(* Logix 5000 project; controller GracoPd2kDual_Example vendor 1 type 14 code 196 rev 32.11; software revision 32.04 *)
// CompactLogix Controller

TASK MainTask (continuous, watchdog 500 ms) : GRACO_PD2K   // Task Description

MODULES
   Local : vendor 1 type 14 code 196 (5069 0, rev 32.11)
      GRACO_PD2K : ETHERNET-MODULE (Ethernet 192.168.1.50, rev 1.1, Output RPI 100 ms)   // Graco Example PD2K
           GRACO_PD2K:I.Data[0]   // PD2K1 mix unit 1 system mode
           GRACO_PD2K:I.Data[10]   // PD2K1 mix unit 1 actual pump 1 flow rate (cc/min)
           GRACO_PD2K:I.Data[11]   // PD2K1 mix unit 1 actual pump 2 flow rate (cc/min)
           GRACO_PD2K:I.Data[12]   // PD2K1 mix unit 1 actual pump 1 pressure (psi)
           GRACO_PD2K:I.Data[13]   // PD2K1 mix unit 1 actual pump 2 pressure (psi)
           GRACO_PD2K:I.Data[14]   // PD2K1 mix unit 1 active recipe number
           GRACO_PD2K:I.Data[15]   // PD2K1 mix unit 1 active recipe material A
           GRACO_PD2K:I.Data[16]   // PD2K1 mix unit 1 active recipe material B
           GRACO_PD2K:I.Data[17]   // PD2K1 mix unit 1 active recipe flush sequence A
           GRACO_PD2K:I.Data[18]   // PD2K1 mix unit 1 active recipe flush sequence B
           GRACO_PD2K:I.Data[19]   // PD2K1 mix unit 1 active mix ratio SP (A*100 : B)
           GRACO_PD2K:I.Data[1]   // PD2K1 mix unit 1 event flag
           GRACO_PD2K:I.Data[20]   // PD2K1 mix unit 1 active pot life time SP (min)
           GRACO_PD2K:I.Data[21]   // PD2K1 mix unit 1 active job number
           GRACO_PD2K:I.Data[22]   // PD2K1 mix unit 1 job material A sprayed volume (cc)
           GRACO_PD2K:I.Data[23]   // PD2K1 mix unit 1 job material B sprayed volume (cc)
           GRACO_PD2K:I.Data[24]   // PD2K1 mix unit 1 job material solvent sprayed volume (cc)
           GRACO_PD2K:I.Data[25]   // PD2K1 mix unit 1 safety interlock status
           GRACO_PD2K:I.Data[26]   // PD2K1 mix unit 2 system mode
           GRACO_PD2K:I.Data[27]   // PD2K1 mix unit 2 event flag
           GRACO_PD2K:I.Data[28]   // PD2K1 mix unit 2 actual mix flow/pressure (cc/min in flow mode, psi in pressure mode)
           GRACO_PD2K:I.Data[29]   // PD2K1 mix unit 2 actual mix ratio (A*100 : B)
           GRACO_PD2K:I.Data[2]   // PD2K1 mix unit 1 actual mix flow/pressure (cc/min in flow mode, psi in pressure mode)
           GRACO_PD2K:I.Data[30]   // PD2K1 mix unit 2 actual pot life remaining (sec)
           GRACO_PD2K:I.Data[31]   // PD2K1 mix unit 2 gun 2 trigger status
           GRACO_PD2K:I.Data[32]   // PD2K1 mix unit 2 pump 3 status
           GRACO_PD2K:I.Data[33]   // PD2K1 mix unit 2 pump 4 status
           GRACO_PD2K:I.Data[34]   // PD2K1 mix unit 2 pump 3 current material
           GRACO_PD2K:I.Data[35]   // PD2K1 mix unit 2 pump 4 current material
           GRACO_PD2K:I.Data[36]   // PD2K1 mix unit 2 actual pump 3 flow rate (cc/min)
           GRACO_PD2K:I.Data[37]   // PD2K1 mix unit 2 actual pump 4 flow rate (cc/min)
           GRACO_PD2K:I.Data[38]   // PD2K1 mix unit 2 actual pump 3 pressure (psi)
           GRACO_PD2K:I.Data[39]   // PD2K1 mix unit 2 actual pump 4 pressure (psi)
           GRACO_PD2K:I.Data[3]   // PD2K1 mix unit 1 actual mix ratio (A*100 : B)
           GRACO_PD2K:I.Data[40]   // PD2K1 mix unit 2 active recipe number
           GRACO_PD2K:I.Data[41]   // PD2K1 mix unit 2 active recipe material A
           GRACO_PD2K:I.Data[42]   // PD2K1 mix unit 2 active recipe material B
           GRACO_PD2K:I.Data[43]   // PD2K1 mix unit 2 active recipe flush sequence A
           GRACO_PD2K:I.Data[44]   // PD2K1 mix unit 2 active recipe flush sequence B
           GRACO_PD2K:I.Data[45]   // PD2K1 mix unit 2 active mix ratio SP (A*100 : B)
           GRACO_PD2K:I.Data[46]   // PD2K1 mix unit 2 active pot life time SP (min)
           GRACO_PD2K:I.Data[47]   // PD2K1 mix unit 2 active job number
           GRACO_PD2K:I.Data[48]   // PD2K1 mix unit 2 job material A sprayed volume (cc)
           GRACO_PD2K:I.Data[49]   // PD2K1 mix unit 2 job material B sprayed volume (cc)
           GRACO_PD2K:I.Data[4]   // PD2K1 mix unit 1 actual pot life remaining (sec)
           GRACO_PD2K:I.Data[50]   // PD2K1 mix unit 2 job material solvent sprayed volume (cc)
           GRACO_PD2K:I.Data[51]   // PD2K1 mix unit 2 safety interlock status
           GRACO_PD2K:I.Data[52]   // PD2K1 DCS return 0
           GRACO_PD2K:I.Data[53]   // PD2K1 DCS return 1
           GRACO_PD2K:I.Data[54]   // PD2K1 DCS return 2
           GRACO_PD2K:I.Data[55]   // PD2K1 DCS return 3
           GRACO_PD2K:I.Data[56]   // PD2K1 DCS return 4
           GRACO_PD2K:I.Data[57]   // PD2K1 DCS return 5
           GRACO_PD2K:I.Data[58]   // PD2K1 DCS return 6
           GRACO_PD2K:I.Data[59]   // PD2K1 DCS return 7
           GRACO_PD2K:I.Data[5]   // PD2K1 mix unit 1 gun 1 trigger status
           GRACO_PD2K:I.Data[60]   // PD2K1 DCS return 8
           GRACO_PD2K:I.Data[61]   // PD2K1 DCS acknowledge
           GRACO_PD2K:I.Data[6]   // PD2K1 mix unit 1 pump 1 status
           GRACO_PD2K:I.Data[7]   // PD2K1 mix unit 1 pump 2 status
           GRACO_PD2K:I.Data[8]   // PD2K1 mix unit 1 pump 1 current material
           GRACO_PD2K:I.Data[9]   // PD2K1 mix unit 1 pump 2 current material
           GRACO_PD2K:I   // PD2K1 module status
           GRACO_PD2K:O.Data[0]   // PD2K1 mix unit 1 system mode command
           GRACO_PD2K:O.Data[10]   // PD2K1 mix unit 2 system mode command
           GRACO_PD2K:O.Data[11]   // PD2K1 mix unit 2 clear active alarm/deviation
           GRACO_PD2K:O.Data[12]   // PD2K1 mix unit 2 goto recipe number
           GRACO_PD2K:O.Data[13]   // PD2K1 mix unit 2 mix control setpoint (cc/min in flow mode, psi in pressure mode)
           GRACO_PD2K:O.Data[14]   // PD2K1 mix unit 2 mix fill setpoint (cc/min in flow mode, psi in pressure mode)
           GRACO_PD2K:O.Data[15]   // PD2K1 mix unit 2 pump flush sequence number / prime material number
           GRACO_PD2K:O.Data[16]   // PD2K1 mix unit 2 pump flush/prime command
           GRACO_PD2K:O.Data[17]   // PD2K1 mix unit 2 job complete command
           GRACO_PD2K:O.Data[18]   // PD2K1 mix unit 2 gun 2 trigger
           GRACO_PD2K:O.Data[19]   // PD2K1 mix unit 2 fluid control mode (0=flow, 1=pressure)
           GRACO_PD2K:O.Data[1]   // PD2K1 mix unit 1 clear active alarm/deviation
           GRACO_PD2K:O.Data[20]   // PD2K1 DCS argument 0
           GRACO_PD2K:O.Data[21]   // PD2K1 DCS argument 1
           GRACO_PD2K:O.Data[22]   // PD2K1 DCS argument 2
           GRACO_PD2K:O.Data[23]   // PD2K1 DCS argument 3
           GRACO_PD2K:O.Data[24]   // PD2K1 DCS argument 4
           GRACO_PD2K:O.Data[25]   // PD2K1 DCS argument 5
           GRACO_PD2K:O.Data[26]   // PD2K1 DCS argument 6
           GRACO_PD2K:O.Data[27]   // PD2K1 DCS argument 7
           GRACO_PD2K:O.Data[28]   // PD2K1 DCS argument 8
           GRACO_PD2K:O.Data[29]   // PD2K1 DCS command
           GRACO_PD2K:O.Data[2]   // PD2K1 mix unit 1 goto recipe number
           GRACO_PD2K:O.Data[3]   // PD2K1 mix unit 1 mix control setpoint (cc/min in flow mode, psi in pressure mode)
           GRACO_PD2K:O.Data[4]   // PD2K1 mix unit 1 mix fill setpoint (cc/min in flow mode, psi in pressure mode)
           GRACO_PD2K:O.Data[5]   // PD2K1 mix unit 1 pump flush sequence number / prime material number
           GRACO_PD2K:O.Data[6]   // PD2K1 mix unit 1 pump flush/prime command
           GRACO_PD2K:O.Data[7]   // PD2K1 mix unit 1 job complete command
           GRACO_PD2K:O.Data[8]   // PD2K1 mix unit 1 gun 1 trigger
           GRACO_PD2K:O.Data[9]   // PD2K1 mix unit 1 fluid control mode (0=flow, 1=pressure)
           GRACO_PD2K:O   // PD2K1 module commands
           GRACO_PD2K:C   // PD2K1 module configuration
END_MODULES

TYPE GracoCore_TypeDateTime :
STRUCT
   year : DINT;   // year (yyyy)
   month : DINT;   // month (1=January, 2=February...12=December)
   dayOfMonth : DINT;   // day of the month (1-31)
   dayOfWeek : DINT;   // day of the week (1=Monday, 2=Tuesday...7=Sunday)
   hour : DINT;   // hour (0-23)
   min : DINT;   // min (0-59)
   sec : DINT;   // second (0-59)
END_STRUCT
END_TYPE

TYPE GracoPD2K_TypeRecipe :
STRUCT
   materialA : DINT;   // Material number for component A
   materialB : DINT;   // Material number for component B
   flushSeqA : DINT;   // Flush sequence number for component A
   flushSeqB : DINT;   // Flush sequence number for component B
   mixRatioSP : DINT;   // Mix ratio setpoint (A*100 : B)
   potLifeTimeSP : DINT;   // Pot life time setpoint (min)
END_STRUCT
END_TYPE

TYPE GracoPd2kDual_TypePd2kDualStatus :
STRUCT
   gunTriggerStatus1 : BOOL;   // gun 1 trigger status (1 = on)
   gunTriggerStatus2 : BOOL;   // gun 2 trigger status (1 = on)
   mixUnit1 : GracoPd2kDual_TypePd2kMixUnitStatus;   // mix unit 1
   mixUnit2 : GracoPd2kDual_TypePd2kMixUnitStatus;   // mix unit 2
   pump1 : GracoPd2kDual_TypePd2kPump;   // pump 1
   pump2 : GracoPd2kDual_TypePd2kPump;   // pump 2
   pump3 : GracoPd2kDual_TypePd2kPump;   // pump 3
   pump4 : GracoPd2kDual_TypePd2kPump;   // pump 4
   dcsReturn0 : DINT;   // DCS return 0
   dcsReturn1 : DINT;   // DCS return 1
   dcsReturn2 : DINT;   // DCS return 2
   dcsReturn3 : DINT;   // DCS return 3
   dcsReturn4 : DINT;   // DCS return 4
   dcsReturn5 : DINT;   // DCS return 5
   dcsReturn6 : DINT;   // DCS return 6
   dcsReturn7 : DINT;   // DCS return 7
   dcsReturn8 : DINT;   // DCS return 8
   dcsAck : DINT;   // DCS acknowledge
END_STRUCT
END_TYPE

TYPE GracoPd2kDual_TypePd2kMixUnitStatus :
STRUCT
   eventFlag : BOOL;   // event flag
   standby : BOOL;   // in standby
   interlockStatus : BOOL;   // interlock status
   systemMode : DINT;   // system mode
   systemModeFlags : GracoPd2kDual_TypePd2kSystemModeFlags;   // system mode flags
   actualMixFlow : DINT;   // actual mix flow (cc/min)
   actualMixRatio : DINT;   // actual mix ratio
   actualPotLifeRemaining : DINT;   // actual pot life remaining
   activeRecipeNum : DINT;   // active recipe number
   activeMaterialA : DINT;   // active material A
   activeMaterialB : DINT;   // active material B
   activeFlushSeqA : DINT;   // active flush sequence A
   activeFlushSeqB : DINT;   // active flush sequence B
   activeRatioSP : DINT;   // active ratio SP
   activePotLifeSP : DINT;   // active pot life SP
   activeJobNum : DINT;   // active job number
   jobSprayVolA : DINT;   // job sprayed volume A (cc)
   jobSprayVolB : DINT;   // job sprayed volume B (cc)
   jobSolventVol : DINT;   // job solvent volume used (cc)
END_STRUCT
END_TYPE

TYPE GracoPd2kDual_TypePd2kPump :
STRUCT
   status : DINT;   // pump status
   statusFlags : GracoPd2kDual_TypePd2kPumpStatusFlags;   // pump status flags
   actualMaterial : DINT;   // actual material number
   actualFlowRate : DINT;   // actual flow rate (cc/min)
   actualFluidPres : DINT;   // actual fluid pressure (psi)
END_STRUCT
END_TYPE

TYPE GracoPd2kDual_TypePd2kPumpStatusFlags :
STRUCT
   off : BOOL;   // off
   standby : BOOL;   // in standby
   busy : BOOL;   // busy
   flushing : BOOL;   // flushing
   priming : BOOL;   // priming
END_STRUCT
END_TYPE

TYPE GracoPd2kDual_TypePd2kSystemModeFlags :
STRUCT
   pumpOff : BOOL;   // pump off
   colorChange : BOOL;   // color change enabled
   colorChangePurgeA : BOOL;   // color change purging component A
   colorChangePurgeB : BOOL;   // color change purging component B
   colorChangeFilling : BOOL;   // color change filling
   mixFill : BOOL;   // mix fill
   mix : BOOL;   // mixing
   mixIdle : BOOL;   // mix idle
   purgeA : BOOL;   // purging component A
   purgeB : BOOL;   // purging component B
   standbyMixReady : BOOL;   // standby mix ready
   standbyFillReady : BOOL;   // standby fill ready
   standbyMixNotReady : BOOL;   // standby mix not ready
   standbyAlarm : BOOL;   // standby alarm
   lineFillingFlushing : BOOL;   // line is filling or flushing
   pumpPrimeFlush : BOOL;   // pump is priming or flushing
   maintCalibration : BOOL;   // maintenance/calibration
   mixSolventPush : BOOL;   // mix solvent push
END_STRUCT
END_TYPE

TYPE STRING4 :   // string type
STRUCT
   LEN : DINT;
   DATA : SINT[4];
END_STRUCT
END_TYPE

TYPE STRING9 :   // string type
STRUCT
   LEN : DINT;
   DATA : SINT[9];
END_STRUCT
END_TYPE

ADD_ON_INSTRUCTION GracoCore_DecodeDateTime   (* revision 1.0 *)
// Help:
// Convert from Graco-formatted date and time data into a UDT.
VAR_IN_OUT
   dateSource : DINT; {required}
   timeSource : DINT; {required}
   dateTimeDest : GracoCore_TypeDateTime; {required}
END_VAR
VAR
   buffer : DINT; {access None}
END_VAR

ROUTINE Logic   (* ladder *)
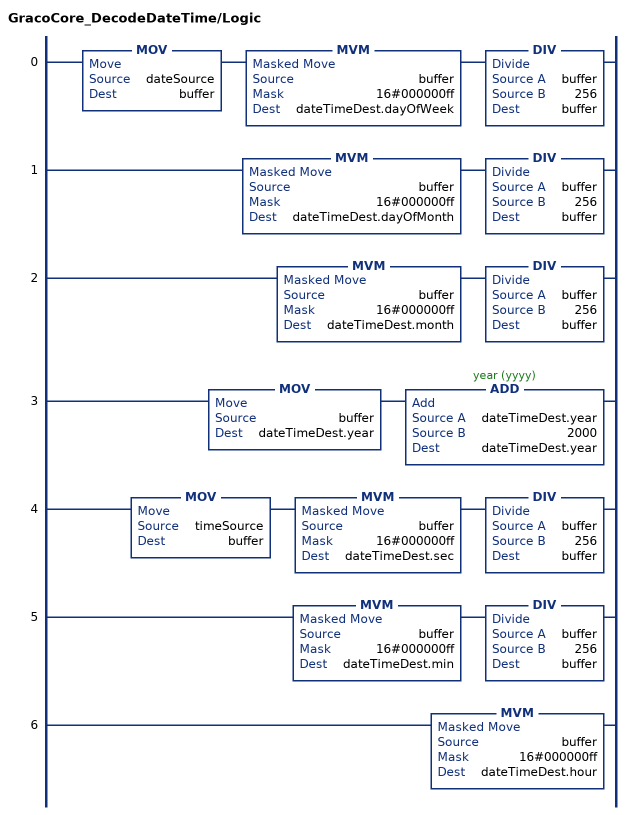
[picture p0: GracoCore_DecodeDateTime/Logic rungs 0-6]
   0: MOV(dateSource,buffer)MVM(buffer,16#000000ff,dateTimeDest.dayOfWeek)DIV(buffer,256,buffer);
   1: MVM(buffer,16#000000ff,dateTimeDest.dayOfMonth)DIV(buffer,256,buffer);
   2: MVM(buffer,16#000000ff,dateTimeDest.month)DIV(buffer,256,buffer);
   3: MOV(buffer,dateTimeDest.year)ADD(dateTimeDest.year,2000,dateTimeDest.year);
   4: MOV(timeSource,buffer)MVM(buffer,16#000000ff,dateTimeDest.sec)DIV(buffer,256,buffer);
   5: MVM(buffer,16#000000ff,dateTimeDest.min)DIV(buffer,256,buffer);
   6: MVM(buffer,16#000000ff,dateTimeDest.hour);
END_ROUTINE
END_ADD_ON_INSTRUCTION

ADD_ON_INSTRUCTION GracoCore_DecodeEventCode   (* revision 1.0 *)
// Help:
// Parses an event code String (max 4 characters) into a series of ASCII values stored in DINTs. These can then be written to a Graco CGM.
VAR_IN_OUT
   source : DINT; {required}
   dest : STRING4; {required}
END_VAR
VAR
   buffer : DINT; {access None}
END_VAR

ROUTINE Logic   (* ladder *)
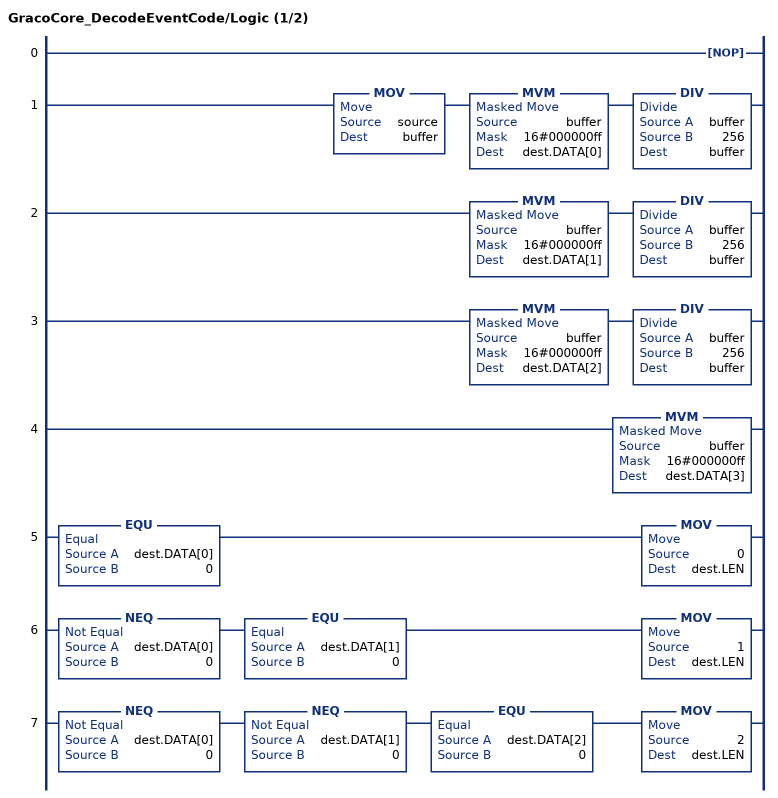
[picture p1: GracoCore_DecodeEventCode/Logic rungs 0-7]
   0: NOP();
   1: MOV(source,buffer)MVM(buffer,16#000000ff,dest.DATA[0])DIV(buffer,256,buffer);
   2: MVM(buffer,16#000000ff,dest.DATA[1])DIV(buffer,256,buffer);
   3: MVM(buffer,16#000000ff,dest.DATA[2])DIV(buffer,256,buffer);
   4: MVM(buffer,16#000000ff,dest.DATA[3]);
   5: EQU(dest.DATA[0],0)MOV(0,dest.LEN);
   6: NEQ(dest.DATA[0],0)EQU(dest.DATA[1],0)MOV(1,dest.LEN);
   7: NEQ(dest.DATA[0],0)NEQ(dest.DATA[1],0)EQU(dest.DATA[2],0)MOV(2,dest.LEN);
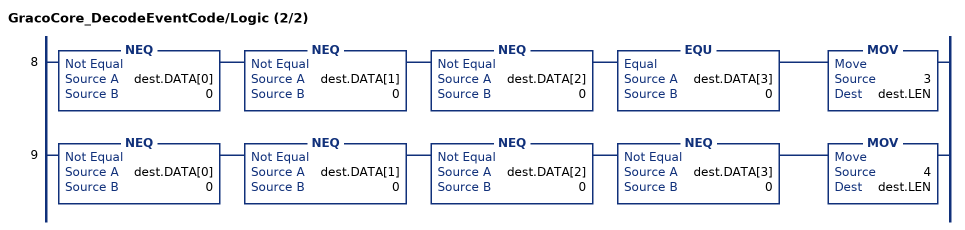
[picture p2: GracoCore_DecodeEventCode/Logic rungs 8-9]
   8: NEQ(dest.DATA[0],0)NEQ(dest.DATA[1],0)NEQ(dest.DATA[2],0)EQU(dest.DATA[3],0)MOV(3,dest.LEN);
   9: NEQ(dest.DATA[0],0)NEQ(dest.DATA[1],0)NEQ(dest.DATA[2],0)NEQ(dest.DATA[3],0)MOV(4,dest.LEN);
END_ROUTINE
END_ADD_ON_INSTRUCTION

ADD_ON_INSTRUCTION GracoCore_DecodeUserID   (* revision 1.0 *)
// Help:
// Parses a user ID from a series of characters stored in DINTs into a Rockwell String (9 characters max).
VAR_IN_OUT
   source1 : DINT; {required}
   source2 : DINT; {required}
   source3 : DINT; {required}
   dest : STRING9; {required}
END_VAR
VAR
   buffer : DINT; {access None}
END_VAR

ROUTINE Logic   (* ladder *)
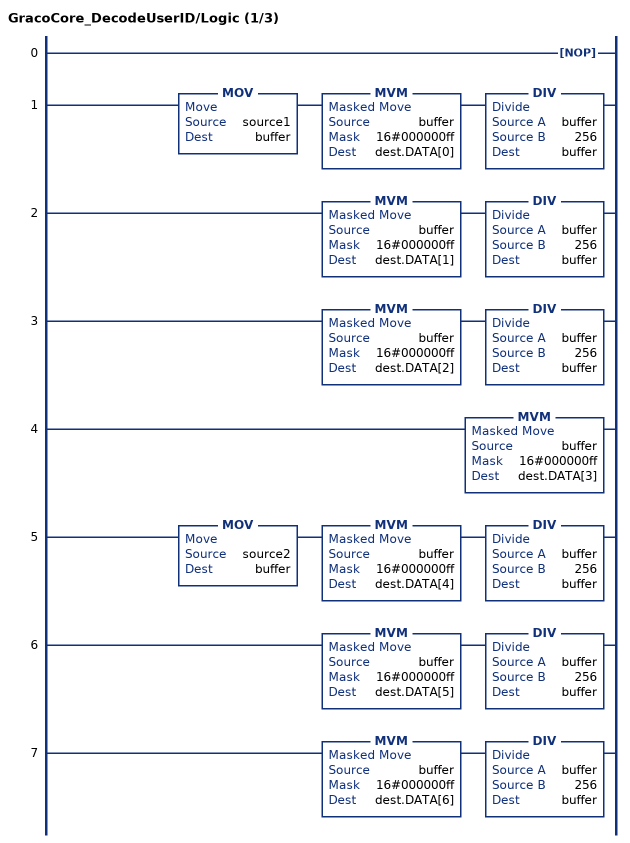
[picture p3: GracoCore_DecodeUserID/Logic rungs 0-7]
   0: NOP();
   1: MOV(source1,buffer)MVM(buffer,16#000000ff,dest.DATA[0])DIV(buffer,256,buffer);
   2: MVM(buffer,16#000000ff,dest.DATA[1])DIV(buffer,256,buffer);
   3: MVM(buffer,16#000000ff,dest.DATA[2])DIV(buffer,256,buffer);
   4: MVM(buffer,16#000000ff,dest.DATA[3]);
   5: MOV(source2,buffer)MVM(buffer,16#000000ff,dest.DATA[4])DIV(buffer,256,buffer);
   6: MVM(buffer,16#000000ff,dest.DATA[5])DIV(buffer,256,buffer);
   7: MVM(buffer,16#000000ff,dest.DATA[6])DIV(buffer,256,buffer);
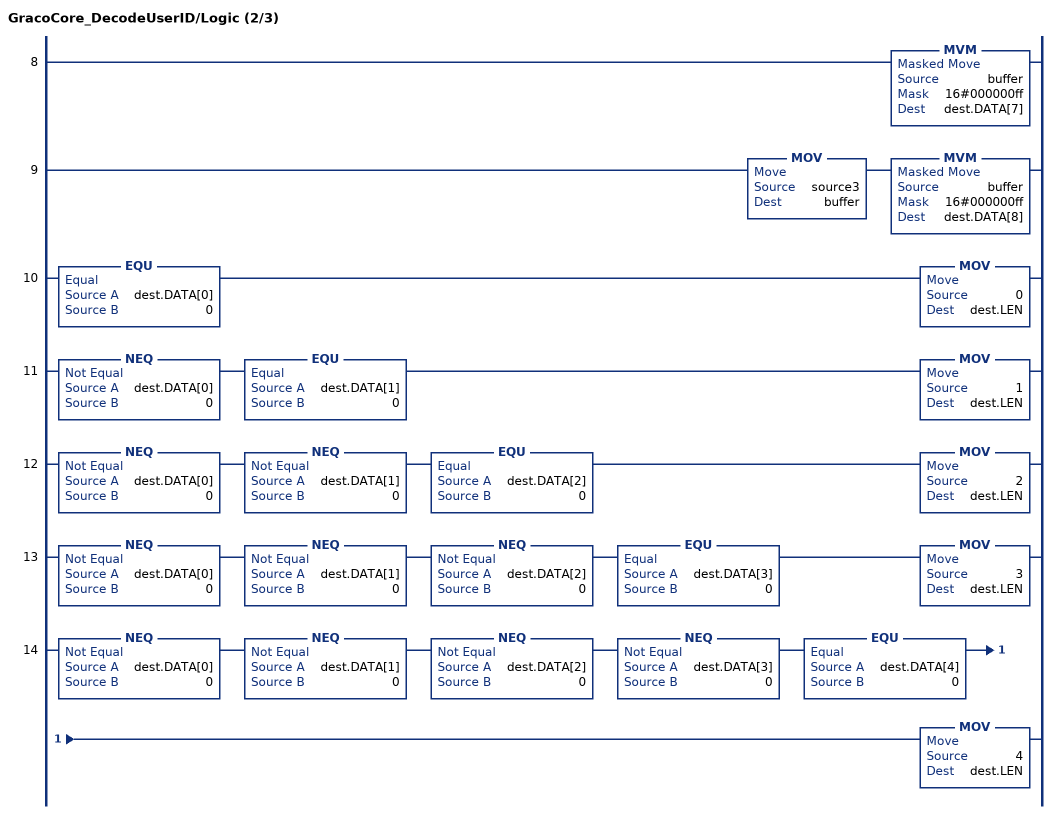
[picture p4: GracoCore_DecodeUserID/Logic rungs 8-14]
   8: MVM(buffer,16#000000ff,dest.DATA[7]);
   9: MOV(source3,buffer)MVM(buffer,16#000000ff,dest.DATA[8]);
   10: EQU(dest.DATA[0],0)MOV(0,dest.LEN);
   11: NEQ(dest.DATA[0],0)EQU(dest.DATA[1],0)MOV(1,dest.LEN);
   12: NEQ(dest.DATA[0],0)NEQ(dest.DATA[1],0)EQU(dest.DATA[2],0)MOV(2,dest.LEN);
   13: NEQ(dest.DATA[0],0)NEQ(dest.DATA[1],0)NEQ(dest.DATA[2],0)EQU(dest.DATA[3],0)MOV(3,dest.LEN);
   14: NEQ(dest.DATA[0],0)NEQ(dest.DATA[1],0)NEQ(dest.DATA[2],0)NEQ(dest.DATA[3],0)EQU(dest.DATA[4],0)MOV(4,dest.LEN);
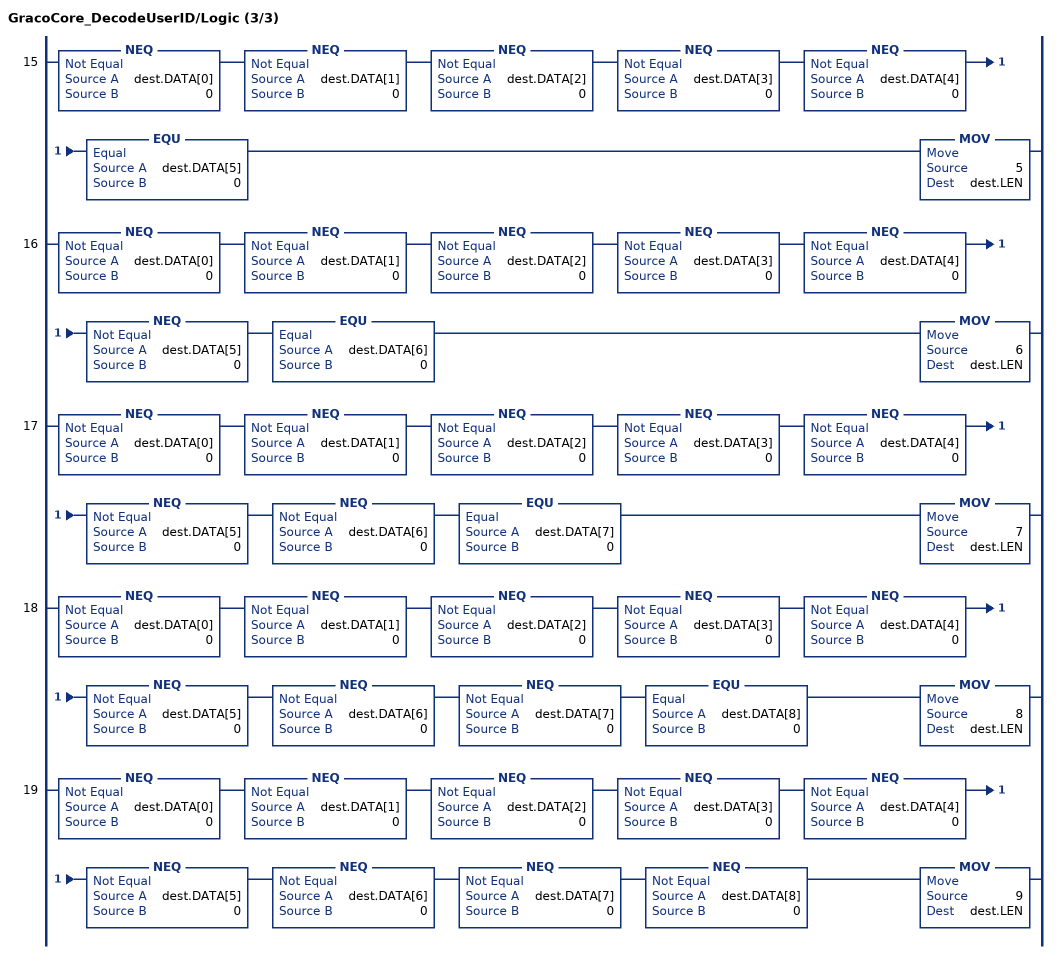
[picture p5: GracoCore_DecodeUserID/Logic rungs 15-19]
   15: NEQ(dest.DATA[0],0)NEQ(dest.DATA[1],0)NEQ(dest.DATA[2],0)NEQ(dest.DATA[3],0)NEQ(dest.DATA[4],0)EQU(dest.DATA[5],0)MOV(5,dest.LEN);
   16: NEQ(dest.DATA[0],0)NEQ(dest.DATA[1],0)NEQ(dest.DATA[2],0)NEQ(dest.DATA[3],0)NEQ(dest.DATA[4],0)NEQ(dest.DATA[5],0)EQU(dest.DATA[6],0)MOV(6,dest.LEN);
   17: NEQ(dest.DATA[0],0)NEQ(dest.DATA[1],0)NEQ(dest.DATA[2],0)NEQ(dest.DATA[3],0)NEQ(dest.DATA[4],0)NEQ(dest.DATA[5],0)NEQ(dest.DATA[6],0)EQU(dest.DATA[7],0)MOV(7,dest.LEN);
   18: NEQ(dest.DATA[0],0)NEQ(dest.DATA[1],0)NEQ(dest.DATA[2],0)NEQ(dest.DATA[3],0)NEQ(dest.DATA[4],0)NEQ(dest.DATA[5],0)NEQ(dest.DATA[6],0)NEQ(dest.DATA[7],0)EQU(dest.DATA[8],0)MOV(8,dest.LEN);
   19: NEQ(dest.DATA[0],0)NEQ(dest.DATA[1],0)NEQ(dest.DATA[2],0)NEQ(dest.DATA[3],0)NEQ(dest.DATA[4],0)NEQ(dest.DATA[5],0)NEQ(dest.DATA[6],0)NEQ(dest.DATA[7],0)NEQ(dest.DATA[8],0)MOV(9,dest.LEN);
END_ROUTINE
END_ADD_ON_INSTRUCTION

ADD_ON_INSTRUCTION GracoCore_EncodeUserID   (* revision 1.0 *)
// Help:
// Parses a user ID String (max 9 characters) into a series of ASCII values stored in DINTs. These can then be written to a Graco CGM.
VAR_IN_OUT
   source : STRING9; {required}
   dest1 : DINT; {required}
   dest2 : DINT; {required}
   dest3 : DINT; {required}
END_VAR
VAR
   buffer : DINT; {access None}
END_VAR

ROUTINE Logic   (* ladder *)
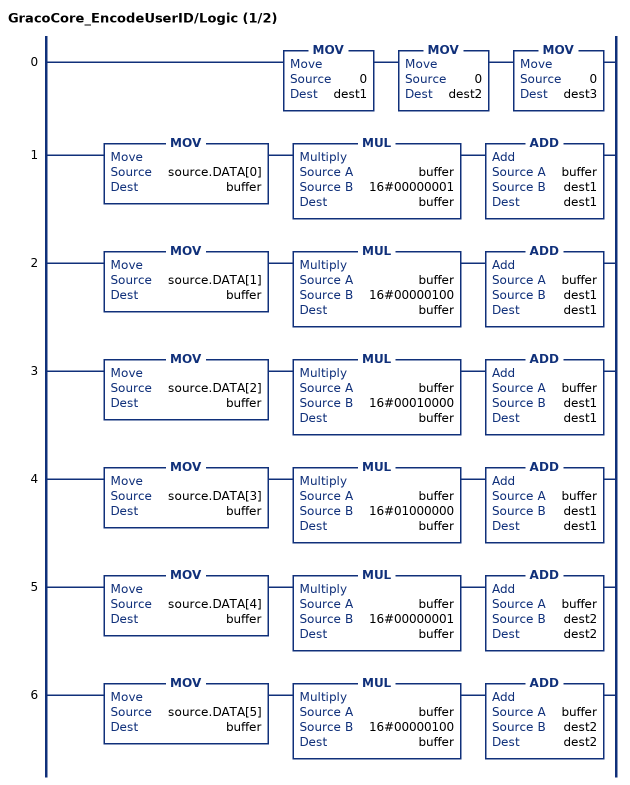
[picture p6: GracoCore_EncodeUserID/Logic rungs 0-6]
   0: MOV(0,dest1)MOV(0,dest2)MOV(0,dest3);
   1: MOV(source.DATA[0],buffer)MUL(buffer,16#00000001,buffer)ADD(buffer,dest1,dest1);
   2: MOV(source.DATA[1],buffer)MUL(buffer,16#00000100,buffer)ADD(buffer,dest1,dest1);
   3: MOV(source.DATA[2],buffer)MUL(buffer,16#00010000,buffer)ADD(buffer,dest1,dest1);
   4: MOV(source.DATA[3],buffer)MUL(buffer,16#01000000,buffer)ADD(buffer,dest1,dest1);
   5: MOV(source.DATA[4],buffer)MUL(buffer,16#00000001,buffer)ADD(buffer,dest2,dest2);
   6: MOV(source.DATA[5],buffer)MUL(buffer,16#00000100,buffer)ADD(buffer,dest2,dest2);
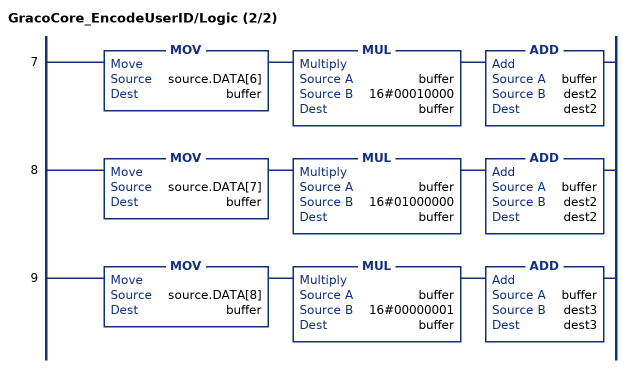
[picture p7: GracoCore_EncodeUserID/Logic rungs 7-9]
   7: MOV(source.DATA[6],buffer)MUL(buffer,16#00010000,buffer)ADD(buffer,dest2,dest2);
   8: MOV(source.DATA[7],buffer)MUL(buffer,16#01000000,buffer)ADD(buffer,dest2,dest2);
   9: MOV(source.DATA[8],buffer)MUL(buffer,16#00000001,buffer)ADD(buffer,dest3,dest3);
END_ROUTINE
END_ADD_ON_INSTRUCTION

ADD_ON_INSTRUCTION GracoCore_Step   (* revision 1.0 *)
// Help:
// An implementation of the step pattern, useful for sequences in ladder logic.
VAR_INPUT
   doneTrigger : BOOL; {access None, visible}
   preCond : BOOL; {visible}
END_VAR
VAR_OUTPUT
   isDone : BOOL; {access Read Only, visible}
   isRunning : BOOL; {access None, visible}
END_VAR

ROUTINE Logic   (* ladder *)
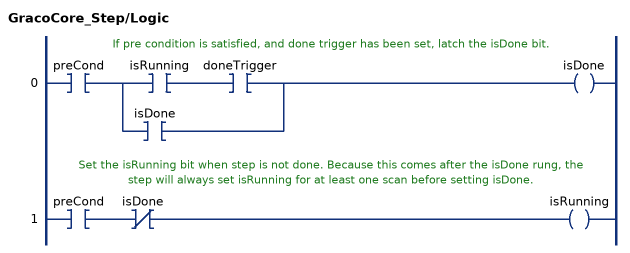
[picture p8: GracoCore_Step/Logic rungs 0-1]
   // If pre condition is satisfied, and done trigger has been set, latch the isDone bit.
   0: XIC(preCond)[XIC(isRunning) XIC(doneTrigger) ,XIC(isDone) ]OTE(isDone);
   // Set the isRunning bit when step is not done. Because this comes after the isDone rung, the step will always set isRunning for at least one scan before setting isDone.
   1: XIC(preCond)XIO(isDone)OTE(isRunning);
END_ROUTINE
END_ADD_ON_INSTRUCTION

ADD_ON_INSTRUCTION GracoPd2kDual_MainCtrl   (* revision 1.0 *)
// Help:
// Provides several inputs for controlling the PD2K proportioner (e.g. system mode, setpoints).
// The enable input must be on for any other inputs to take effect. The boolean command inputs each function like execute inputs, meaning the command will automatically reset these once set to true.
// The current control mode setting (pressure or flow) determines which of the setpoint inputs are written to the PD2K system. This switches automatically when the control mode is changed.
// State Codes:
// * 0000 (IDLE) - Idle
// * 3000 (VALID) - Valid
// * 8000 (ERROR) - Invalid mix unit number
VAR_INPUT
   i_clearAlarm : BOOL; {visible}   // Clear alarm
   i_completeJob : BOOL; {visible}   // Complete job
   i_ctrlMode : BOOL; {visible}   // Ctrl mode SP (0=flow, 1=pressure)
   i_enable : BOOL; {visible}   // Enable command
   i_mix : BOOL; {visible}   // Goto mix
   i_mixFill : BOOL; {visible}   // Goto mix fill
   i_powerOff : BOOL; {visible}   // Power off
   i_powerOn : BOOL; {visible}   // Power on
   i_quickStop : BOOL; {visible}   // Goto quick stop
   i_recipePurge : BOOL; {visible}   // Goto recipe purge
   i_standby : BOOL; {visible}   // Goto standby
   i_mixUnitNum : DINT; {visible}   // Mix unit number (1-2)
   i_flowCtrlSP : DINT; {visible}   // Flow control setpoint (cc/min)
   i_presCtrlSP : DINT; {visible}   // Pressure control setpoint (psi)
END_VAR
VAR_IN_OUT
   io_moduleStatus : DINT[62]; {required}   // Data from module to PLC
   io_moduleCmds : DINT[30]; {required}   // Data from PLC to module
END_VAR
VAR_OUTPUT
   o_aborted : BOOL; {access Read Only, visible}   // Command aborted flag
   o_busy : BOOL; {access Read Only, visible}   // Busy flag
   o_error : BOOL; {access Read Only, visible}   // Error flag
   o_valid : BOOL; {access Read Only, visible}   // Command valid flag
   o_state : DINT; {access Read Only, visible}   // Command state
END_VAR
VAR
   clearAlmPBTmr : TIMER := (PRE := 250); {access None}   // Clear alarm pushbutton timer
   jobCompletePBTmr : TIMER := (PRE := 250); {access None}   // Job complete input timer
   mixFillPBTmr : TIMER := (PRE := 250); {access None}   // Mix fill input timer
   mixPBTmr : TIMER := (PRE := 250); {access None}   // Mix input timer
   ons : DINT; {access None}   // oneshot
   powerOnPBTmr : TIMER := (PRE := 250); {access None}   // Power on input timer
   pumpIsOff : BOOL; {access None}   // Pump is off
   purgePBTmr : TIMER := (PRE := 250); {access None}   // Purge input timer
   quickStopPBTmr : TIMER := (PRE := 250); {access None}   // Quick stop input timer
   isStandby : BOOL; {access None}   // System is in standby
   toStandbyPBTmr : TIMER := (PRE := 250); {access None}   // Standby input timer
   _mixUnitNum : DINT; {access None}   // Mix unit number (internal)
   mixUnitNumOK : BOOL; {access None}   // Mix unit number OK
   systemCmdAvailable : BOOL; {access None}   // System command register is available
   powerOnOffSetTrigger : BOOL; {access None}   // Power on/off set trigger
   powerOnOffResetTrigger : BOOL; {access None}   // Power on/off reset trigger
   quickStopSetTrigger : BOOL; {access None}   // Quick stop set trigger
   quickStopResetTrigger : BOOL; {access None}   // Quick stop reset trigger
   mixFillSetTrigger : BOOL; {access None}   // Mix fill set trigger
   mixFillResetTrigger : BOOL; {access None}   // Mix fill reset trigger
   mixSetTrigger : BOOL; {access None}   // Mix set trigger
   mixResetTrigger : BOOL; {access None}   // Mix reset trigger
   toStandbySetTrigger : BOOL; {access None}   // Standby set trigger
   toStandbyResetTrigger : BOOL; {access None}   // Standby reset trigger
   purgeSetTrigger : BOOL; {access None}   // Purge set trigger
   purgeResetTrigger : BOOL; {access None}   // Purge reset trigger
   state_idle : DINT; {access None}
   state_checkInputs : DINT; {access None}
   state_update : DINT; {access None}
   _nextState : DINT; {access None}
   state_errorInvalidMixUnitNum : DINT; {access None}
END_VAR

ROUTINE Logic   (* ladder *)
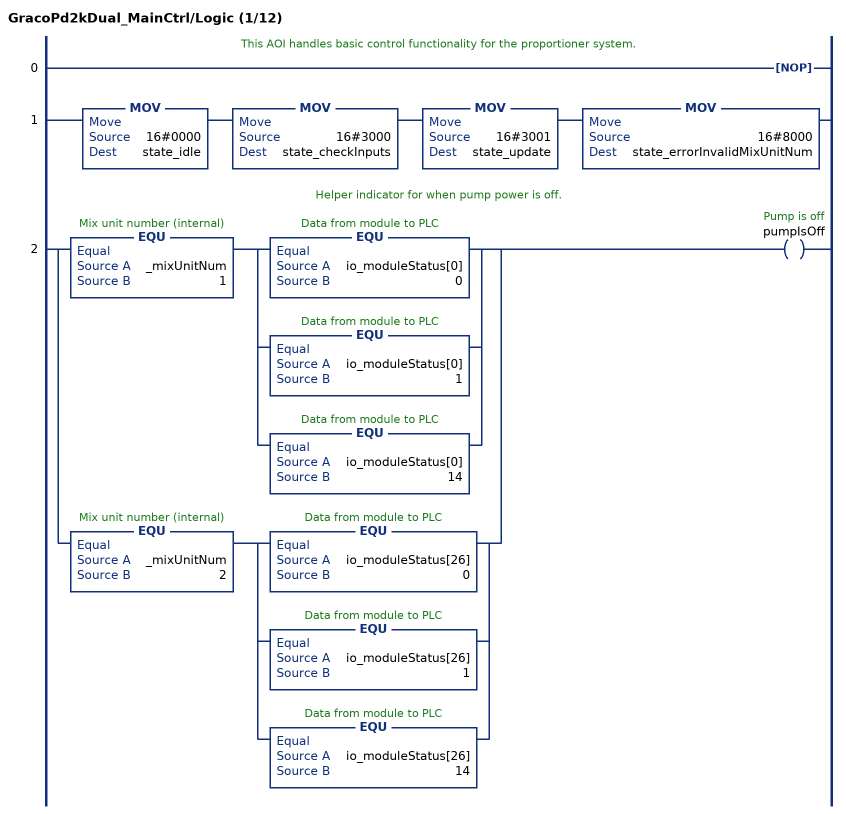
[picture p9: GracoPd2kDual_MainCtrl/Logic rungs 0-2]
   // This AOI handles basic control functionality for the proportioner system.
   0: NOP();
   1: MOV(16#0000,state_idle)MOV(16#3000,state_checkInputs)MOV(16#3001,state_update)MOV(16#8000,state_errorInvalidMixUnitNum);
   // Helper indicator for when pump power is off.
   2: [EQU(_mixUnitNum,1) [EQU(io_moduleStatus[0],0) ,EQU(io_moduleStatus[0],1) ,EQU(io_moduleStatus[0],14) ] ,EQU(_mixUnitNum,2) [EQU(io_moduleStatus[26],0) ,EQU(io_moduleStatus[26],1) ,EQU(io_moduleStatus[26],14) ] ]OTE(pumpIsOff);
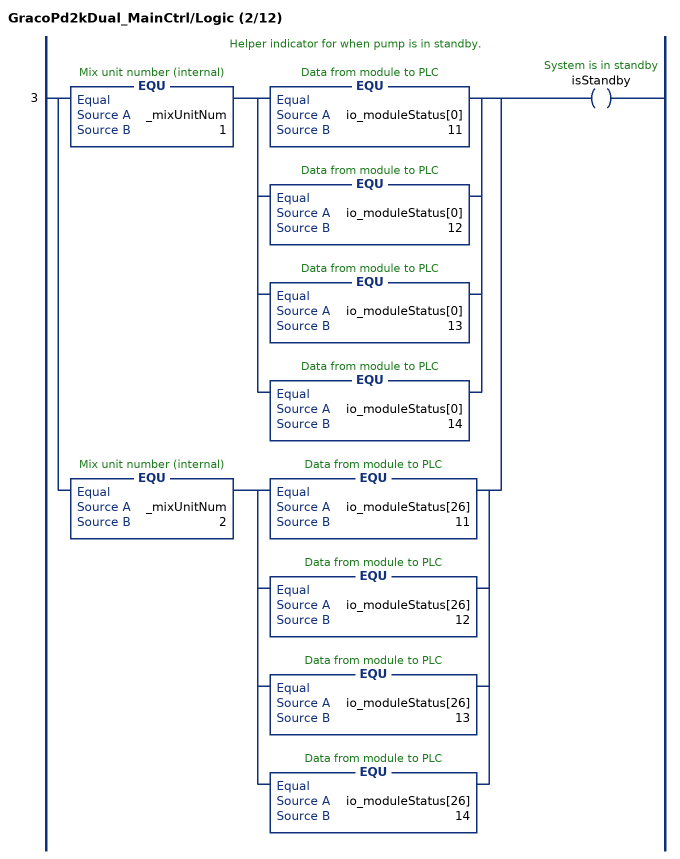
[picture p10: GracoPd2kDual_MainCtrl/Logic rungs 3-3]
   // Helper indicator for when pump is in standby.
   3: [EQU(_mixUnitNum,1) [EQU(io_moduleStatus[0],11) ,EQU(io_moduleStatus[0],12) ,EQU(io_moduleStatus[0],13) ,EQU(io_moduleStatus[0],14) ] ,EQU(_mixUnitNum,2) [EQU(io_moduleStatus[26],11) ,EQU(io_moduleStatus[26],12) ,EQU(io_moduleStatus[26],13) ,EQU(io_moduleStatus[26],14) ] ]OTE(isStandby);
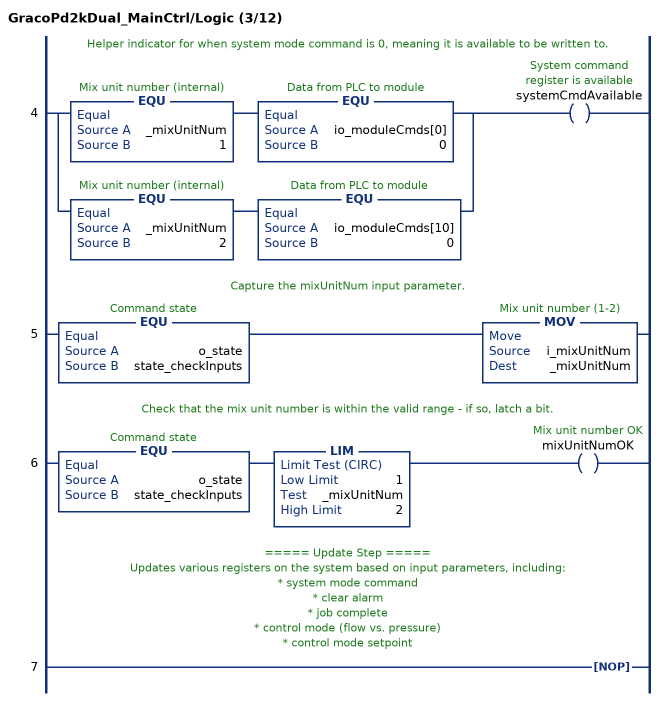
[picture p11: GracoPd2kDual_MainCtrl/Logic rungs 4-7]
   // Helper indicator for when system mode command is 0, meaning it is available to be written to.
   4: [EQU(_mixUnitNum,1) EQU(io_moduleCmds[0],0) ,EQU(_mixUnitNum,2) EQU(io_moduleCmds[10],0) ]OTE(systemCmdAvailable);
   // Capture the mixUnitNum input parameter.
   5: EQU(o_state,state_checkInputs)MOV(i_mixUnitNum,_mixUnitNum);
   // Check that the mix unit number is within the valid range - if so, latch a bit.
   6: EQU(o_state,state_checkInputs)LIM(1,_mixUnitNum,2)OTE(mixUnitNumOK);
   // ===== Update Step =====
   // Updates various registers on the system based on input parameters, including:
   // * system mode command
   // * clear alarm
   // * job complete
   // * control mode (flow vs. pressure)
   // * control mode setpoint
   7: NOP();
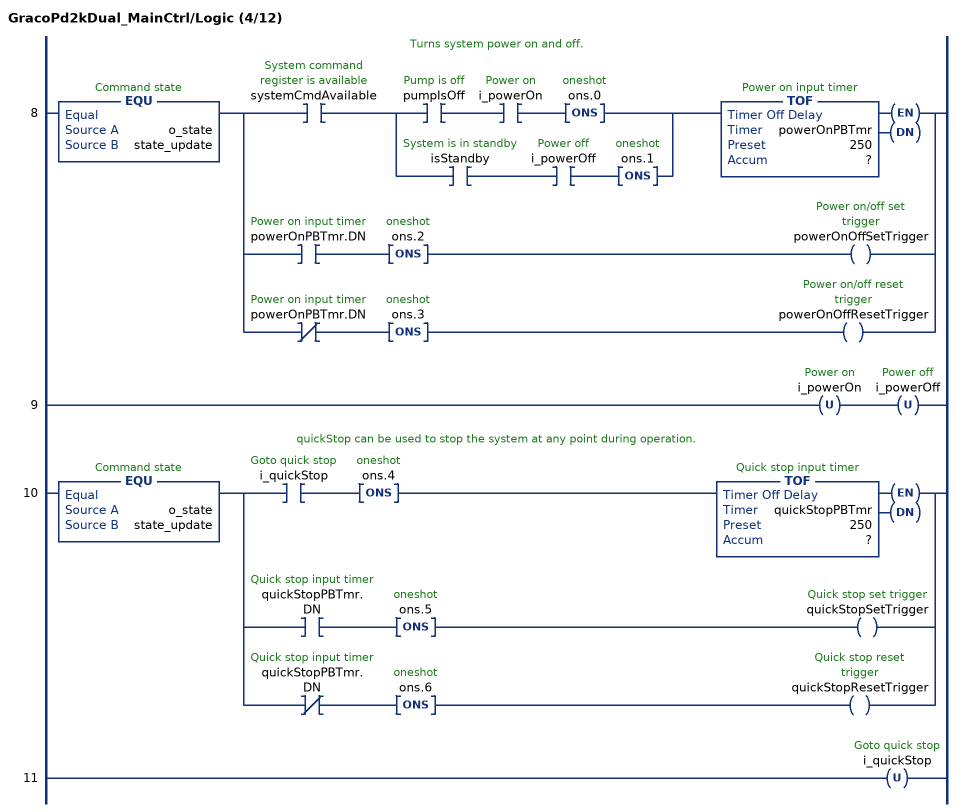
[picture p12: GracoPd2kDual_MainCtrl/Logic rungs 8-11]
   // Turns system power on and off.
   8: EQU(o_state,state_update)[XIC(systemCmdAvailable) [XIC(pumpIsOff) XIC(i_powerOn) ONS(ons.0) ,XIC(isStandby) XIC(i_powerOff) ONS(ons.1) ] TOF(powerOnPBTmr,?,?) ,XIC(powerOnPBTmr.DN) ONS(ons.2) OTE(powerOnOffSetTrigger) ,XIO(powerOnPBTmr.DN) ONS(ons.3) OTE(powerOnOffResetTrigger) ];
   9: OTU(i_powerOn)OTU(i_powerOff);
   // quickStop can be used to stop the system at any point during operation.
   10: EQU(o_state,state_update)[XIC(i_quickStop) ONS(ons.4) TOF(quickStopPBTmr,?,?) ,XIC(quickStopPBTmr.DN) ONS(ons.5) OTE(quickStopSetTrigger) ,XIO(quickStopPBTmr.DN) ONS(ons.6) OTE(quickStopResetTrigger) ];
   11: OTU(i_quickStop);
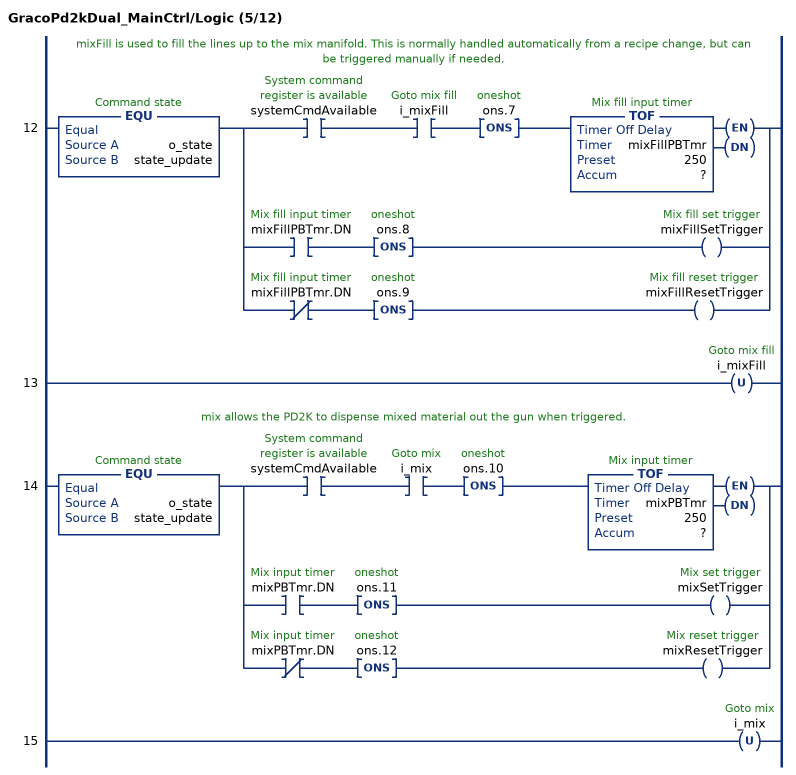
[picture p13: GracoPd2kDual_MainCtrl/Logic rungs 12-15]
   // mixFill is used to fill the lines up to the mix manifold. This is normally handled automatically from a recipe change, but can be triggered manually if needed.
   12: EQU(o_state,state_update)[XIC(systemCmdAvailable) XIC(i_mixFill) ONS(ons.7) TOF(mixFillPBTmr,?,?) ,XIC(mixFillPBTmr.DN) ONS(ons.8) OTE(mixFillSetTrigger) ,XIO(mixFillPBTmr.DN) ONS(ons.9) OTE(mixFillResetTrigger) ];
   13: OTU(i_mixFill);
   // mix allows the PD2K to dispense mixed material out the gun when triggered.
   14: EQU(o_state,state_update)[XIC(systemCmdAvailable) XIC(i_mix) ONS(ons.10) TOF(mixPBTmr,?,?) ,XIC(mixPBTmr.DN) ONS(ons.11) OTE(mixSetTrigger) ,XIO(mixPBTmr.DN) ONS(ons.12) OTE(mixResetTrigger) ];
   15: OTU(i_mix);
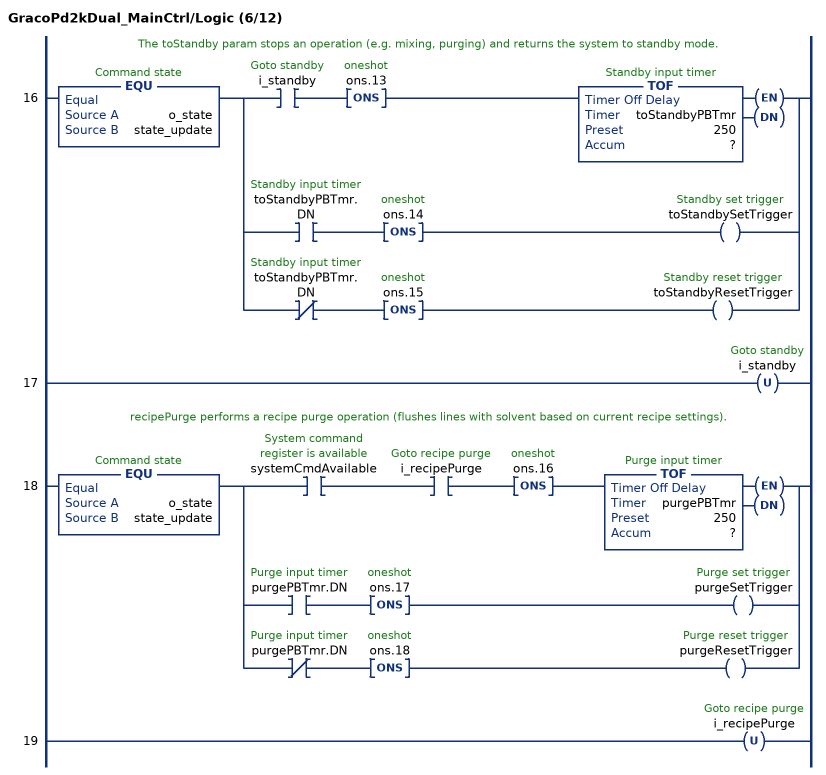
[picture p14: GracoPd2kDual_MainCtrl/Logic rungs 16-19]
   // The toStandby param stops an operation (e.g. mixing, purging) and returns the system to standby mode.
   16: EQU(o_state,state_update)[XIC(i_standby) ONS(ons.13) TOF(toStandbyPBTmr,?,?) ,XIC(toStandbyPBTmr.DN) ONS(ons.14) OTE(toStandbySetTrigger) ,XIO(toStandbyPBTmr.DN) ONS(ons.15) OTE(toStandbyResetTrigger) ];
   17: OTU(i_standby);
   // recipePurge performs a recipe purge operation (flushes lines with solvent based on current recipe settings).
   18: EQU(o_state,state_update)[XIC(systemCmdAvailable) XIC(i_recipePurge) ONS(ons.16) TOF(purgePBTmr,?,?) ,XIC(purgePBTmr.DN) ONS(ons.17) OTE(purgeSetTrigger) ,XIO(purgePBTmr.DN) ONS(ons.18) OTE(purgeResetTrigger) ];
   19: OTU(i_recipePurge);
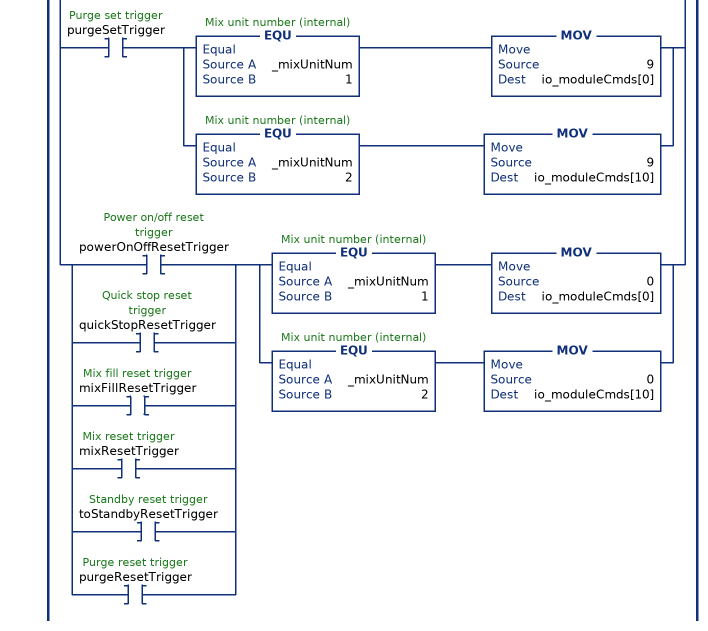
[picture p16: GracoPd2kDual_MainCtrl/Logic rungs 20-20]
   // Write the system mode command register depending on the mix unit number and any triggers driven from the input parameters.
   20: [XIC(powerOnOffSetTrigger) [EQU(_mixUnitNum,1) MOV(1,io_moduleCmds[0]) ,EQU(_mixUnitNum,2) MOV(1,io_moduleCmds[10]) ] ,XIC(quickStopSetTrigger) [EQU(_mixUnitNum,1) MOV(2,io_moduleCmds[0]) ,EQU(_mixUnitNum,2) MOV(2,io_moduleCmds[10]) ] ,XIC(mixFillSetTrigger) [EQU(_mixUnitNum,1) MOV(4,io_moduleCmds[0]) ,EQU(_mixUnitNum,2) MOV(4,io_moduleCmds[10]) ] ,XIC(mixSetTrigger) [EQU(_mixUnitNum,1) MOV(5,io_moduleCmds[0]) ,EQU(_mixUnitNum,2) MOV(5,io_moduleCmds[10]) ] ,XIC(toStandbySetTrigger) [EQU(_mixUnitNum,1) MOV(8,io_moduleCmds[0]) ,EQU(_mixUnitNum,2) MOV(8,io_moduleCmds[10]) ] ,XIC(purgeSetTrigger) [EQU(_mixUnitNum,1) MOV(9,io_moduleCmds[0]) ,EQU(_mixUnitNum,2) MOV(9,io_moduleCmds[10]) ] ,[XIC(powerOnOffResetTrigger) ,XIC(quickStopResetTrigger) ,XIC(mixFillResetTrigger) ,XIC(mixResetTrigger) ,XIC(toStandbyResetTrigger) ,XIC(purgeResetTrigger) ] [EQU(_mixUnitNum,1) MOV(0,io_moduleCmds[0]) ,EQU(_mixUnitNum,2) MOV(0,io_moduleCmds[10]) ] ];
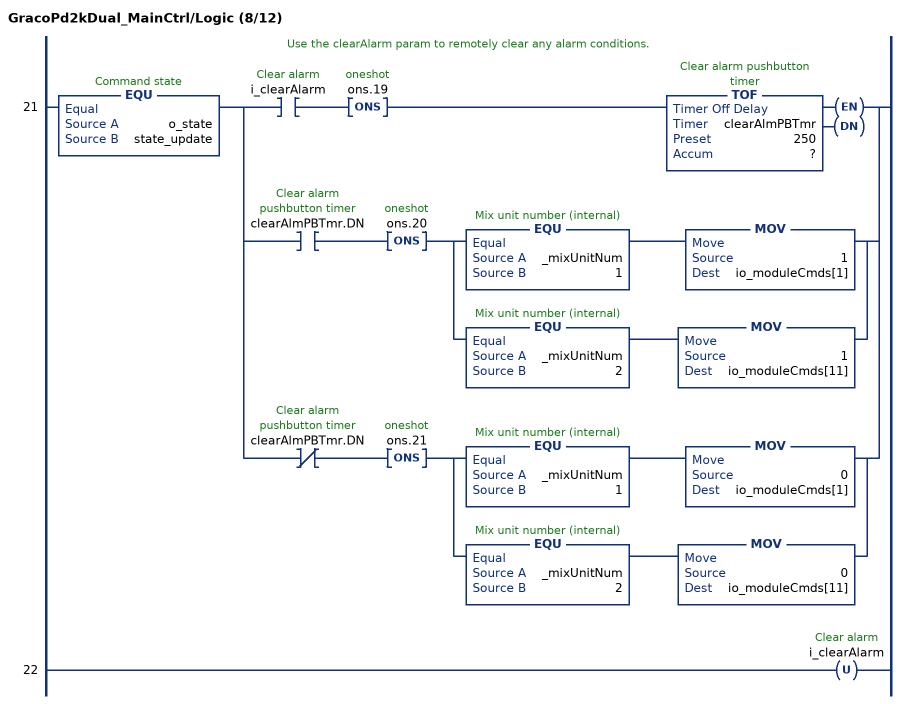
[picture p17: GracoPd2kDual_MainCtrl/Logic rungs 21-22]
   // Use the clearAlarm param to remotely clear any alarm conditions.
   21: EQU(o_state,state_update)[XIC(i_clearAlarm) ONS(ons.19) TOF(clearAlmPBTmr,?,?) ,XIC(clearAlmPBTmr.DN) ONS(ons.20) [EQU(_mixUnitNum,1) MOV(1,io_moduleCmds[1]) ,EQU(_mixUnitNum,2) MOV(1,io_moduleCmds[11]) ] ,XIO(clearAlmPBTmr.DN) ONS(ons.21) [EQU(_mixUnitNum,1) MOV(0,io_moduleCmds[1]) ,EQU(_mixUnitNum,2) MOV(0,io_moduleCmds[11]) ] ];
   22: OTU(i_clearAlarm);
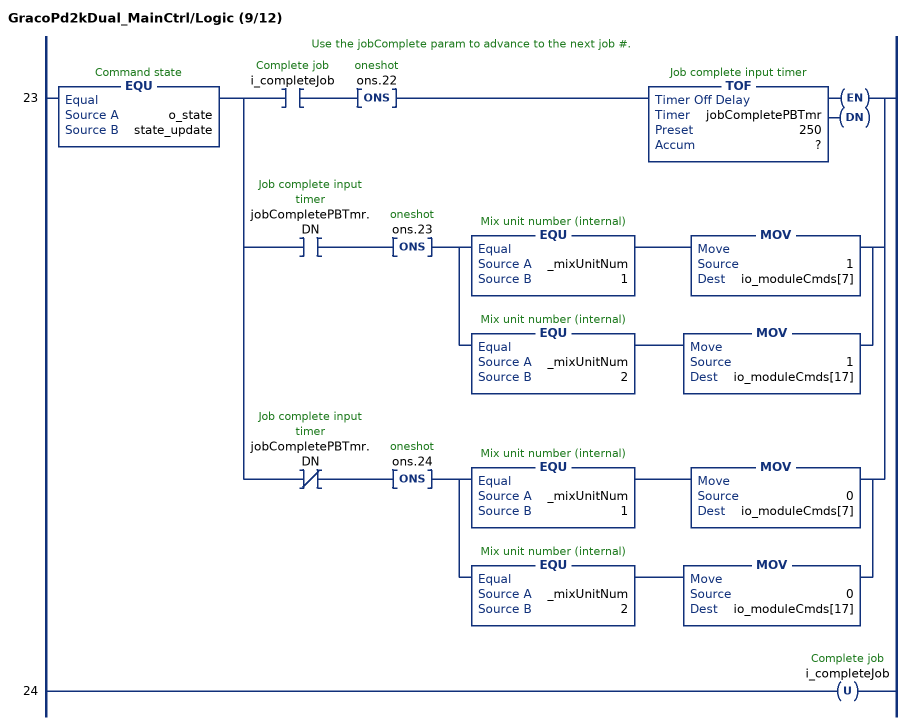
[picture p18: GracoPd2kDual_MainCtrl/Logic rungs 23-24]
   // Use the jobComplete param to advance to the next job #.
   23: EQU(o_state,state_update)[XIC(i_completeJob) ONS(ons.22) TOF(jobCompletePBTmr,?,?) ,XIC(jobCompletePBTmr.DN) ONS(ons.23) [EQU(_mixUnitNum,1) MOV(1,io_moduleCmds[7]) ,EQU(_mixUnitNum,2) MOV(1,io_moduleCmds[17]) ] ,XIO(jobCompletePBTmr.DN) ONS(ons.24) [EQU(_mixUnitNum,1) MOV(0,io_moduleCmds[7]) ,EQU(_mixUnitNum,2) MOV(0,io_moduleCmds[17]) ] ];
   24: OTU(i_completeJob);
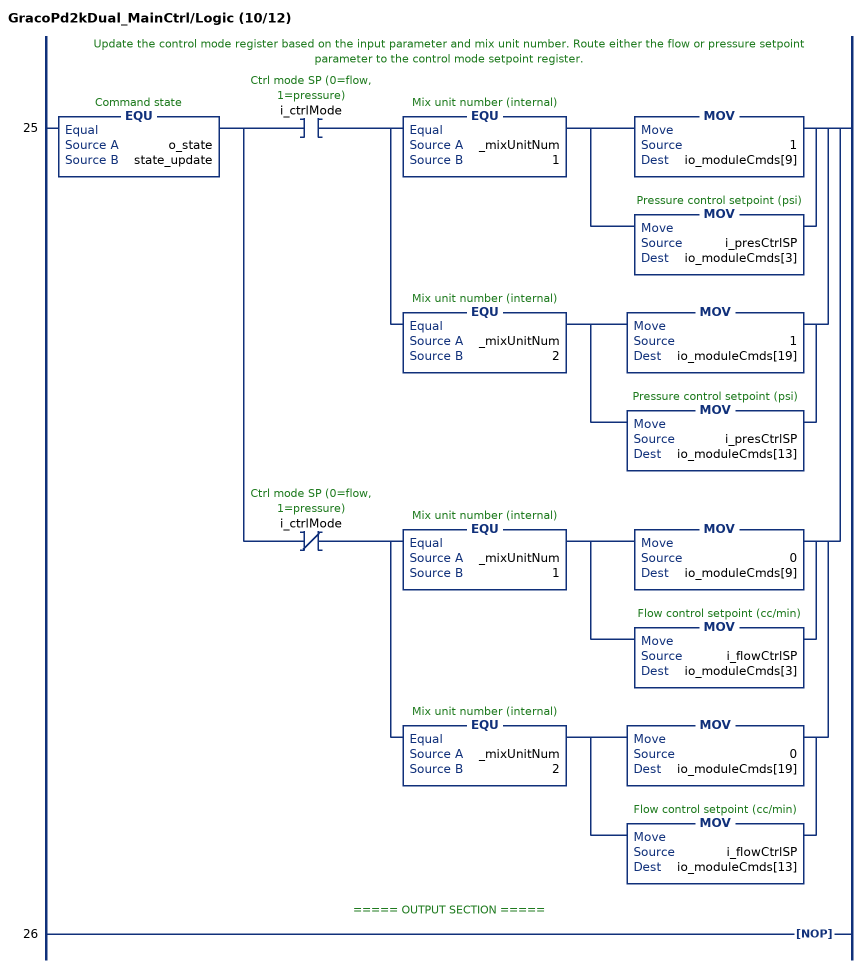
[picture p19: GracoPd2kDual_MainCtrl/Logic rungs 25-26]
   // Update the control mode register based on the input parameter and mix unit number. Route either the flow or pressure setpoint parameter to the control mode setpoint register.
   25: EQU(o_state,state_update)[XIC(i_ctrlMode) [EQU(_mixUnitNum,1) [MOV(1,io_moduleCmds[9]) ,MOV(i_presCtrlSP,io_moduleCmds[3]) ] ,EQU(_mixUnitNum,2) [MOV(1,io_moduleCmds[19]) ,MOV(i_presCtrlSP,io_moduleCmds[13]) ] ] ,XIO(i_ctrlMode) [EQU(_mixUnitNum,1) [MOV(0,io_moduleCmds[9]) ,MOV(i_flowCtrlSP,io_moduleCmds[3]) ] ,EQU(_mixUnitNum,2) [MOV(0,io_moduleCmds[19]) ,MOV(i_flowCtrlSP,io_moduleCmds[13]) ] ] ];
   // ===== OUTPUT SECTION =====
   26: NOP();
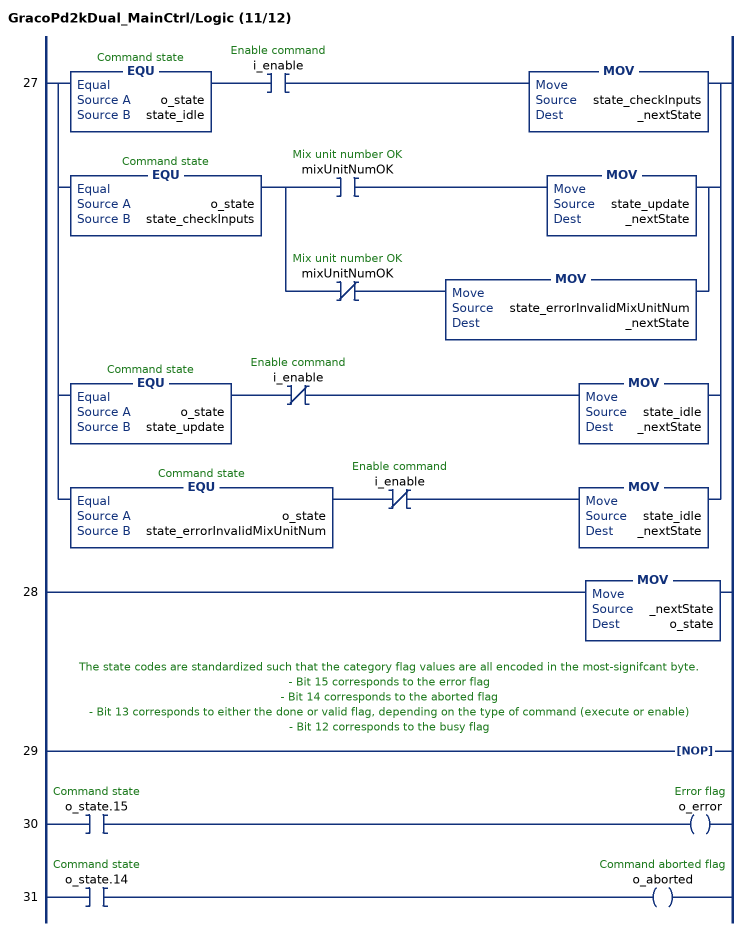
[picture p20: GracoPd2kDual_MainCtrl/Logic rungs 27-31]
   27: [EQU(o_state,state_idle) XIC(i_enable) MOV(state_checkInputs,_nextState) ,EQU(o_state,state_checkInputs) [XIC(mixUnitNumOK) MOV(state_update,_nextState) ,XIO(mixUnitNumOK) MOV(state_errorInvalidMixUnitNum,_nextState) ] ,EQU(o_state,state_update) XIO(i_enable) MOV(state_idle,_nextState) ,EQU(o_state,state_errorInvalidMixUnitNum) XIO(i_enable) MOV(state_idle,_nextState) ];
   28: MOV(_nextState,o_state);
   // The state codes are standardized such that the category flag values are all encoded in the most-signifcant byte.
   // - Bit 15 corresponds to the error flag
   // - Bit 14 corresponds to the aborted flag
   // - Bit 13 corresponds to either the done or valid flag, depending on the type of command (execute or enable)
   // - Bit 12 corresponds to the busy flag
   29: NOP();
   30: XIC(o_state.15)OTE(o_error);
   31: XIC(o_state.14)OTE(o_aborted);
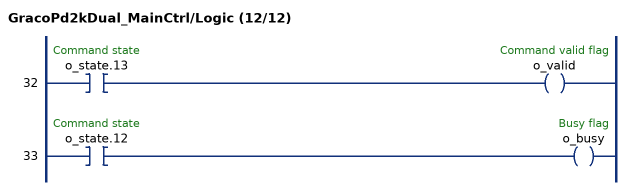
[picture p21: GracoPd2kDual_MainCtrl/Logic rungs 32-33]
   32: XIC(o_state.13)OTE(o_valid);
   33: XIC(o_state.12)OTE(o_busy);
END_ROUTINE
END_ADD_ON_INSTRUCTION
